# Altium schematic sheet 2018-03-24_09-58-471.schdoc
size 267 x 118 mm; SheetNumber: 1; SheetTotal: 1
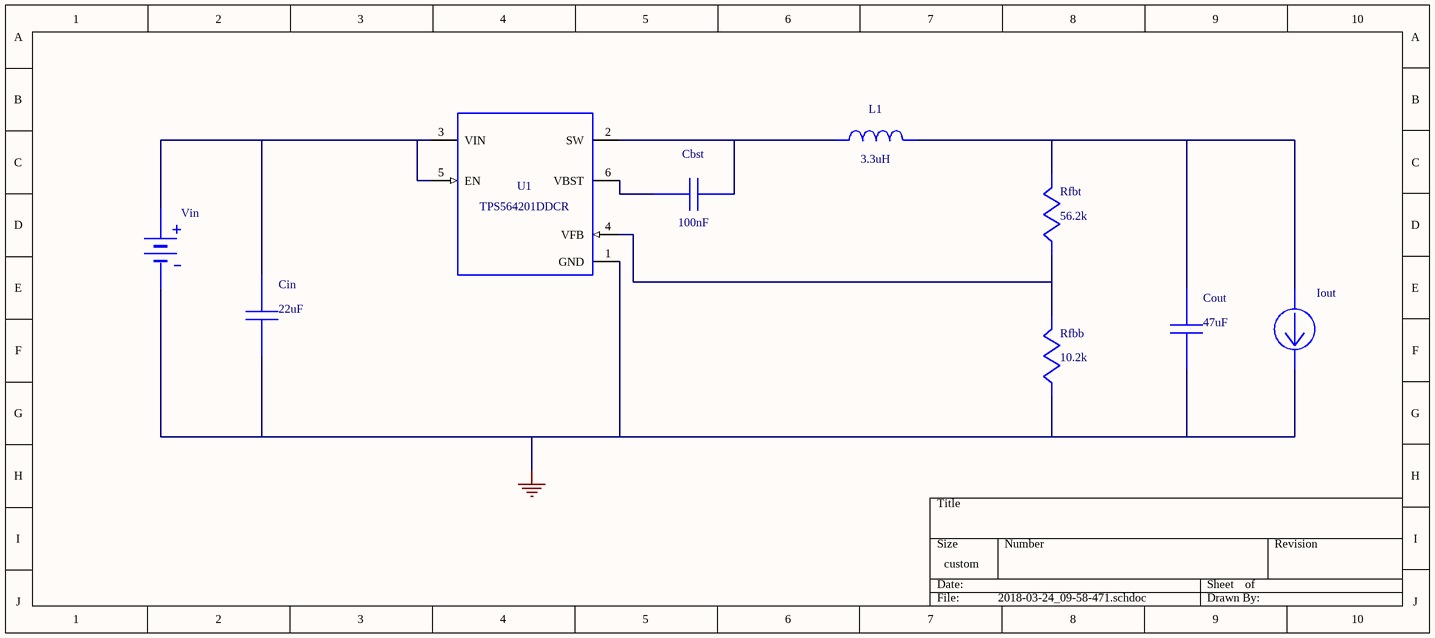
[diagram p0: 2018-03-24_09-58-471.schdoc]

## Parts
Cbst  value 100nF  (hidden comment: C0805C104K3RACTU)
Cin  value 22uF  (hidden comment: GRM32ER61E226KE15L)
Cout  value 47uF  (hidden comment: C3216X5R1E476M160AC)
Iout  WB_CURRENT_LOAD  (value not drawn)
L1  value 3.3uH  (hidden comment: VLP8040T-3R3N)
Rfbb  value 10.2k  (hidden comment: ERJ-6ENF1022V)
Rfbt  value 56.2k  (hidden comment: CRCW040256K2FKED)
U1  TPS564201DDCR
Vin  WB_BATTERY  (value not drawn)

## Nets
0: Cin.2 Cout.2 Iout.2(-) Rfbb.2 U1.1(GND) Vin.2(-)
NetCbst_1: Cbst.1 L1.1 U1.2(SW)
NetCbst_2: Cbst.2 U1.6(VBST)
NetCin_1: Cin.1 U1.3(VIN) U1.5(EN) Vin.1(+)
NetCout_1: Cout.1 Iout.1(+) L1.2 Rfbt.1
NetRfbb_1: Rfbb.1 Rfbt.2 U1.4(VFB)

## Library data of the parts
Cbst = C0805C104K3RACTU: Manufacturer Name: Kemet
Cin = GRM32ER61E226KE15L: GRM32ER61E226KE1; Manufacturer Name: MuRata
Cout = C3216X5R1E476M160AC: C3216X5R1E476M16; Manufacturer Name: TDK
L1 = VLP8040T-3R3N: Unknown; Manufacturer Name: TDK
Rfbb = ERJ-6ENF1022V: Manufacturer Name: Panasonic
Rfbt = CRCW040256K2FKED: Manufacturer Name: Vishay-Dale
U1 = TPS564201DDCR: Manufacturer Name: Texas Instruments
